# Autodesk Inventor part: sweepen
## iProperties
Created: 2010-03
Part Number: sweepen
Document SubType Name: Modeling
Designer: SFleischer
Density: 1 g/cm^3
Author: SFleischer
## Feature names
1. Sweeping1
